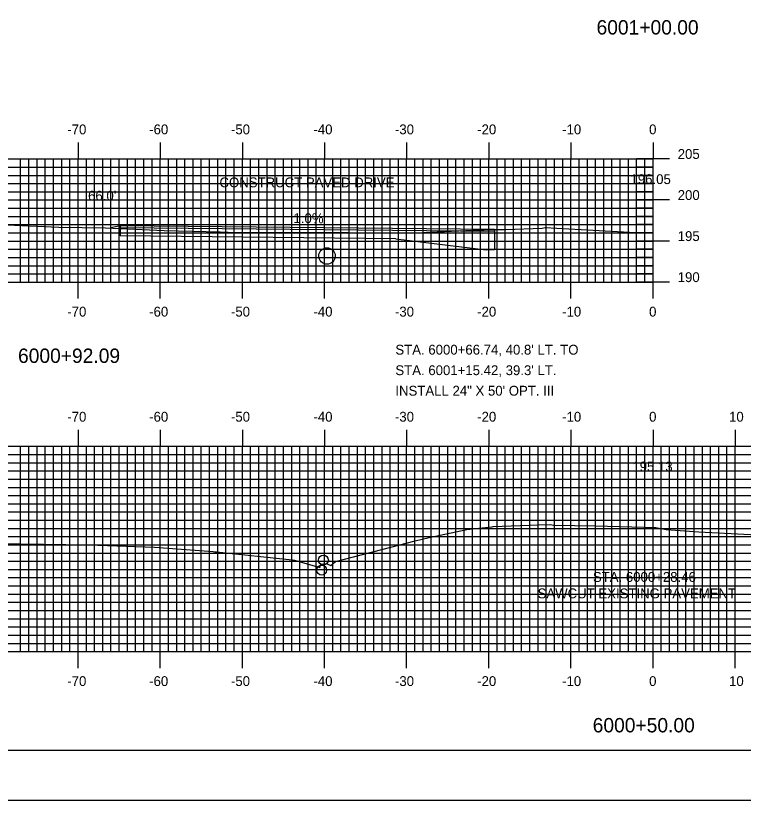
# Model space of a CAD drawing. Extents: x 851300 to 851643, y 366898 to 367118.
# Drawn here: x 851387.9 to 851476.5, y 366898.4 to 366993.9 of the extents above; entities that cross this region are included whole.
import ezdxf

# ---------------------------------------------------------------- set-up
doc = ezdxf.new("R2010")
doc.units = 0
for name, color, linetype in [('ANNOTATION', 7, 'Continuous'), ('BORDER', 7, 'Continuous'), ('D_Drainage_Culvert', 7, 'Continuous'), ('D_Text_Standard', 7, 'Continuous'), ('H_V ANNOTATION', 7, 'Continuous'), ('MAJOR', 7, 'Continuous'), ('MINOR', 7, 'Continuous'), ('PLOT BOUNDARY', 7, 'Continuous'), ('S_Drainage_Invert', 7, 'Continuous'), ('S_Roadway_Centerline', 7, 'Continuous')]:
    doc.layers.add(name, color=color, linetype=linetype)

msp = doc.modelspace()

# ---------------------------------------------------------------- linework, layer by layer
at = {"layer": 'ANNOTATION'}
for p, q in [((851400.605, 366968.345), (851400.605, 366967.095)), ((851434.205, 366966.759), (851445.205, 366965.389))]:
    msp.add_line(p, q, dxfattribs=at)
for points in [[(851446.205, 366967.889), (851400.605, 366968.345), (851399.49, 366968.067)], [(851446.202, 366967.639), (851400.605, 366968.095)], [(851446.205, 366967.889), (851446.205, 366965.389), (851445.205, 366965.389)], [(851434.205, 366966.759), (851400.605, 366967.095)]]:
    msp.add_lwpolyline(points, dxfattribs=at)
at = {"layer": 'BORDER'}
msp.add_lwpolyline([(851315.905, 366904.473), (851635.905, 366904.473), (851635.905, 367114.473), (851315.905, 367114.473)], close=True, dxfattribs=at)
at = {"layer": 'D_Drainage_Culvert'}
msp.add_circle((851425.805, 366964.653), 1, dxfattribs=at)
at = {"layer": 'MAJOR'}
for p, q in [((851395.505, 366978.477), (851395.505, 366976.473)), ((851405.505, 366978.477), (851405.505, 366976.473)), ((851415.505, 366978.477), (851415.505, 366976.473)), ((851425.505, 366978.477), (851425.505, 366976.473)), ((851435.505, 366978.477), (851435.505, 366976.473)), ((851445.505, 366978.477), (851445.505, 366976.473)), ((851455.505, 366978.477), (851455.505, 366976.473)), ((851465.505, 366978.477), (851465.505, 366976.473)), ((851325.505, 366976.473), (851465.505, 366976.473)), ((851325.505, 366976.473), (851465.505, 366976.473)), ((851395.505, 366961.473), (851395.505, 366976.473)), ((851405.505, 366961.473), (851405.505, 366976.473)), ((851415.505, 366961.473), (851415.505, 366976.473)), ((851425.505, 366961.473), (851425.505, 366976.473)), ((851435.505, 366961.473), (851435.505, 366976.473)), ((851445.505, 366961.473), (851445.505, 366976.473)), ((851455.505, 366961.473), (851455.505, 366976.473)), ((851467.509, 366976.473), (851463.501, 366976.473)), ((851465.505, 366961.473), (851465.505, 366976.473)), ((851465.505, 366961.473), (851465.505, 366976.473)), ((851325.505, 366971.473), (851465.505, 366971.473)), ((851467.509, 366971.473), (851463.501, 366971.473)), ((851325.505, 366966.473), (851465.505, 366966.473)), ((851467.509, 366966.473), (851463.501, 366966.473)), ((851325.505, 366961.473), (851465.505, 366961.473)), ((851325.505, 366961.473), (851465.505, 366961.473)), ((851395.505, 366959.469), (851395.505, 366961.473)), ((851405.505, 366959.469), (851405.505, 366961.473)), ((851415.505, 366959.469), (851415.505, 366961.473)), ((851425.505, 366959.469), (851425.505, 366961.473)), ((851435.505, 366959.469), (851435.505, 366961.473)), ((851445.505, 366959.469), (851445.505, 366961.473)), ((851455.505, 366959.469), (851455.505, 366961.473)), ((851467.509, 366961.473), (851463.501, 366961.473)), ((851465.505, 366959.469), (851465.505, 366961.473)), ((851395.505, 366943.477), (851395.505, 366941.473)), ((851405.505, 366943.477), (851405.505, 366941.473)), ((851415.505, 366943.477), (851415.505, 366941.473)), ((851425.505, 366943.477), (851425.505, 366941.473)), ((851435.505, 366943.477), (851435.505, 366941.473)), ((851445.505, 366943.477), (851445.505, 366941.473)), ((851455.505, 366943.477), (851455.505, 366941.473)), ((851465.505, 366943.477), (851465.505, 366941.473)), ((851475.505, 366943.477), (851475.505, 366941.473)), ((851325.505, 366941.473), (851605.505, 366941.473)), ((851325.505, 366941.473), (851605.505, 366941.473)), ((851395.505, 366916.473), (851395.505, 366941.473)), ((851405.505, 366916.473), (851405.505, 366941.473)), ((851415.505, 366916.473), (851415.505, 366941.473)), ((851425.505, 366916.473), (851425.505, 366941.473)), ((851435.505, 366916.473), (851435.505, 366941.473)), ((851445.505, 366916.473), (851445.505, 366941.473)), ((851455.505, 366916.473), (851455.505, 366941.473)), ((851465.505, 366916.473), (851465.505, 366941.473)), ((851475.505, 366916.473), (851475.505, 366941.473)), ((851325.505, 366936.473), (851605.505, 366936.473)), ((851325.505, 366931.473), (851605.505, 366931.473)), ((851325.505, 366926.473), (851605.505, 366926.473)), ((851325.505, 366921.473), (851605.505, 366921.473)), ((851325.505, 366916.473), (851605.505, 366916.473)), ((851325.505, 366916.473), (851605.505, 366916.473)), ((851395.505, 366914.469), (851395.505, 366916.473)), ((851405.505, 366914.469), (851405.505, 366916.473)), ((851415.505, 366914.469), (851415.505, 366916.473)), ((851425.505, 366914.469), (851425.505, 366916.473)), ((851435.505, 366914.469), (851435.505, 366916.473)), ((851445.505, 366914.469), (851445.505, 366916.473)), ((851455.505, 366914.469), (851455.505, 366916.473)), ((851465.505, 366914.469), (851465.505, 366916.473)), ((851475.505, 366914.469), (851475.505, 366916.473))]:
    msp.add_line(p, q, dxfattribs=at)
at = {"layer": 'MINOR'}
for p, q in [((851388.505, 366961.473), (851388.505, 366976.473)), ((851389.505, 366961.473), (851389.505, 366976.473)), ((851390.505, 366961.473), (851390.505, 366976.473)), ((851391.505, 366961.473), (851391.505, 366976.473)), ((851392.505, 366961.473), (851392.505, 366976.473)), ((851393.505, 366961.473), (851393.505, 366976.473)), ((851394.505, 366961.473), (851394.505, 366976.473)), ((851396.505, 366961.473), (851396.505, 366976.473)), ((851397.505, 366961.473), (851397.505, 366976.473)), ((851398.505, 366961.473), (851398.505, 366976.473)), ((851399.505, 366961.473), (851399.505, 366976.473)), ((851400.505, 366961.473), (851400.505, 366976.473)), ((851401.505, 366961.473), (851401.505, 366976.473)), ((851402.505, 366961.473), (851402.505, 366976.473)), ((851403.505, 366961.473), (851403.505, 366976.473)), ((851404.505, 366961.473), (851404.505, 366976.473)), ((851406.505, 366961.473), (851406.505, 366976.473)), ((851407.505, 366961.473), (851407.505, 366976.473)), ((851408.505, 366961.473), (851408.505, 366976.473)), ((851409.505, 366961.473), (851409.505, 366976.473)), ((851410.505, 366961.473), (851410.505, 366976.473)), ((851411.505, 366961.473), (851411.505, 366976.473)), ((851412.505, 366961.473), (851412.505, 366976.473)), ((851413.505, 366961.473), (851413.505, 366976.473)), ((851414.505, 366961.473), (851414.505, 366976.473)), ((851416.505, 366961.473), (851416.505, 366976.473)), ((851417.505, 366961.473), (851417.505, 366976.473)), ((851418.505, 366961.473), (851418.505, 366976.473)), ((851419.505, 366961.473), (851419.505, 366976.473)), ((851420.505, 366961.473), (851420.505, 366976.473)), ((851421.505, 366961.473), (851421.505, 366976.473)), ((851422.505, 366961.473), (851422.505, 366976.473)), ((851423.505, 366961.473), (851423.505, 366976.473)), ((851424.505, 366961.473), (851424.505, 366976.473)), ((851426.505, 366961.473), (851426.505, 366976.473)), ((851427.505, 366961.473), (851427.505, 366976.473)), ((851428.505, 366961.473), (851428.505, 366976.473)), ((851429.505, 366961.473), (851429.505, 366976.473)), ((851430.505, 366961.473), (851430.505, 366976.473)), ((851431.505, 366961.473), (851431.505, 366976.473)), ((851432.505, 366961.473), (851432.505, 366976.473)), ((851433.505, 366961.473), (851433.505, 366976.473)), ((851434.505, 366961.473), (851434.505, 366976.473)), ((851436.505, 366961.473), (851436.505, 366976.473)), ((851437.505, 366961.473), (851437.505, 366976.473)), ((851438.505, 366961.473), (851438.505, 366976.473)), ((851439.505, 366961.473), (851439.505, 366976.473)), ((851440.505, 366961.473), (851440.505, 366976.473)), ((851441.505, 366961.473), (851441.505, 366976.473)), ((851442.505, 366961.473), (851442.505, 366976.473)), ((851443.505, 366961.473), (851443.505, 366976.473)), ((851444.505, 366961.473), (851444.505, 366976.473)), ((851446.505, 366961.473), (851446.505, 366976.473)), ((851447.505, 366961.473), (851447.505, 366976.473)), ((851448.505, 366961.473), (851448.505, 366976.473)), ((851449.505, 366961.473), (851449.505, 366976.473)), ((851450.505, 366961.473), (851450.505, 366976.473)), ((851451.505, 366961.473), (851451.505, 366976.473)), ((851452.505, 366961.473), (851452.505, 366976.473)), ((851453.505, 366961.473), (851453.505, 366976.473)), ((851454.505, 366961.473), (851454.505, 366976.473)), ((851456.505, 366961.473), (851456.505, 366976.473)), ((851457.505, 366961.473), (851457.505, 366976.473)), ((851458.505, 366961.473), (851458.505, 366976.473)), ((851459.505, 366961.473), (851459.505, 366976.473)), ((851460.505, 366961.473), (851460.505, 366976.473)), ((851461.505, 366961.473), (851461.505, 366976.473)), ((851462.505, 366961.473), (851462.505, 366976.473)), ((851463.505, 366961.473), (851463.505, 366976.473)), ((851464.505, 366961.473), (851464.505, 366976.473)), ((851325.505, 366975.473), (851465.505, 366975.473)), ((851465.505, 366975.473), (851463.501, 366975.473)), ((851325.505, 366974.473), (851465.505, 366974.473)), ((851465.505, 366974.473), (851463.501, 366974.473)), ((851325.505, 366973.473), (851465.505, 366973.473)), ((851465.505, 366973.473), (851463.501, 366973.473)), ((851325.505, 366972.473), (851465.505, 366972.473)), ((851465.505, 366972.473), (851463.501, 366972.473)), ((851325.505, 366970.473), (851465.505, 366970.473)), ((851465.505, 366970.473), (851463.501, 366970.473)), ((851325.505, 366969.473), (851465.505, 366969.473)), ((851465.505, 366969.473), (851463.501, 366969.473)), ((851325.505, 366968.473), (851465.505, 366968.473)), ((851465.505, 366968.473), (851463.501, 366968.473)), ((851325.505, 366967.473), (851465.505, 366967.473)), ((851465.505, 366967.473), (851463.501, 366967.473)), ((851325.505, 366965.473), (851465.505, 366965.473)), ((851465.505, 366965.473), (851463.501, 366965.473)), ((851325.505, 366964.473), (851465.505, 366964.473)), ((851465.505, 366964.473), (851463.501, 366964.473)), ((851325.505, 366963.473), (851465.505, 366963.473)), ((851465.505, 366963.473), (851463.501, 366963.473)), ((851325.505, 366962.473), (851465.505, 366962.473)), ((851465.505, 366962.473), (851463.501, 366962.473)), ((851388.505, 366916.473), (851388.505, 366941.473)), ((851389.505, 366916.473), (851389.505, 366941.473)), ((851390.505, 366916.473), (851390.505, 366941.473)), ((851391.505, 366916.473), (851391.505, 366941.473)), ((851392.505, 366916.473), (851392.505, 366941.473)), ((851393.505, 366916.473), (851393.505, 366941.473)), ((851394.505, 366916.473), (851394.505, 366941.473)), ((851396.505, 366916.473), (851396.505, 366941.473)), ((851397.505, 366916.473), (851397.505, 366941.473)), ((851398.505, 366916.473), (851398.505, 366941.473)), ((851399.505, 366916.473), (851399.505, 366941.473)), ((851400.505, 366916.473), (851400.505, 366941.473)), ((851401.505, 366916.473), (851401.505, 366941.473)), ((851402.505, 366916.473), (851402.505, 366941.473)), ((851403.505, 366916.473), (851403.505, 366941.473)), ((851404.505, 366916.473), (851404.505, 366941.473)), ((851406.505, 366916.473), (851406.505, 366941.473)), ((851407.505, 366916.473), (851407.505, 366941.473)), ((851408.505, 366916.473), (851408.505, 366941.473)), ((851409.505, 366916.473), (851409.505, 366941.473)), ((851410.505, 366916.473), (851410.505, 366941.473)), ((851411.505, 366916.473), (851411.505, 366941.473)), ((851412.505, 366916.473), (851412.505, 366941.473)), ((851413.505, 366916.473), (851413.505, 366941.473)), ((851414.505, 366916.473), (851414.505, 366941.473)), ((851416.505, 366916.473), (851416.505, 366941.473)), ((851417.505, 366916.473), (851417.505, 366941.473)), ((851418.505, 366916.473), (851418.505, 366941.473)), ((851419.505, 366916.473), (851419.505, 366941.473)), ((851420.505, 366916.473), (851420.505, 366941.473)), ((851421.505, 366916.473), (851421.505, 366941.473)), ((851422.505, 366916.473), (851422.505, 366941.473)), ((851423.505, 366916.473), (851423.505, 366941.473)), ((851424.505, 366916.473), (851424.505, 366941.473)), ((851426.505, 366916.473), (851426.505, 366941.473)), ((851427.505, 366916.473), (851427.505, 366941.473)), ((851428.505, 366916.473), (851428.505, 366941.473)), ((851429.505, 366916.473), (851429.505, 366941.473)), ((851430.505, 366916.473), (851430.505, 366941.473)), ((851431.505, 366916.473), (851431.505, 366941.473)), ((851432.505, 366916.473), (851432.505, 366941.473)), ((851433.505, 366916.473), (851433.505, 366941.473)), ((851434.505, 366916.473), (851434.505, 366941.473)), ((851436.505, 366916.473), (851436.505, 366941.473)), ((851437.505, 366916.473), (851437.505, 366941.473)), ((851438.505, 366916.473), (851438.505, 366941.473)), ((851439.505, 366916.473), (851439.505, 366941.473)), ((851440.505, 366916.473), (851440.505, 366941.473)), ((851441.505, 366916.473), (851441.505, 366941.473)), ((851442.505, 366916.473), (851442.505, 366941.473)), ((851443.505, 366916.473), (851443.505, 366941.473)), ((851444.505, 366916.473), (851444.505, 366941.473)), ((851446.505, 366916.473), (851446.505, 366941.473)), ((851447.505, 366916.473), (851447.505, 366941.473)), ((851448.505, 366916.473), (851448.505, 366941.473)), ((851449.505, 366916.473), (851449.505, 366941.473)), ((851450.505, 366916.473), (851450.505, 366941.473)), ((851451.505, 366916.473), (851451.505, 366941.473)), ((851452.505, 366916.473), (851452.505, 366941.473)), ((851453.505, 366916.473), (851453.505, 366941.473)), ((851454.505, 366916.473), (851454.505, 366941.473)), ((851456.505, 366916.473), (851456.505, 366941.473)), ((851457.505, 366916.473), (851457.505, 366941.473)), ((851458.505, 366916.473), (851458.505, 366941.473)), ((851459.505, 366916.473), (851459.505, 366941.473)), ((851460.505, 366916.473), (851460.505, 366941.473)), ((851461.505, 366916.473), (851461.505, 366941.473)), ((851462.505, 366916.473), (851462.505, 366941.473)), ((851463.505, 366916.473), (851463.505, 366941.473)), ((851464.505, 366916.473), (851464.505, 366941.473)), ((851466.505, 366916.473), (851466.505, 366941.473)), ((851467.505, 366916.473), (851467.505, 366941.473)), ((851468.505, 366916.473), (851468.505, 366941.473)), ((851469.505, 366916.473), (851469.505, 366941.473)), ((851470.505, 366916.473), (851470.505, 366941.473)), ((851471.505, 366916.473), (851471.505, 366941.473)), ((851472.505, 366916.473), (851472.505, 366941.473)), ((851473.505, 366916.473), (851473.505, 366941.473)), ((851474.505, 366916.473), (851474.505, 366941.473)), ((851325.505, 366940.473), (851605.505, 366940.473)), ((851325.505, 366939.473), (851605.505, 366939.473)), ((851325.505, 366938.473), (851605.505, 366938.473)), ((851325.505, 366937.473), (851605.505, 366937.473)), ((851325.505, 366935.473), (851605.505, 366935.473)), ((851325.505, 366934.473), (851605.505, 366934.473)), ((851325.505, 366933.473), (851605.505, 366933.473)), ((851325.505, 366932.473), (851605.505, 366932.473)), ((851325.505, 366930.473), (851605.505, 366930.473)), ((851325.505, 366929.473), (851605.505, 366929.473)), ((851325.505, 366928.473), (851605.505, 366928.473)), ((851325.505, 366927.473), (851605.505, 366927.473)), ((851325.505, 366925.473), (851605.505, 366925.473)), ((851325.505, 366924.473), (851605.505, 366924.473)), ((851325.505, 366923.473), (851605.505, 366923.473)), ((851325.505, 366922.473), (851605.505, 366922.473)), ((851325.505, 366920.473), (851605.505, 366920.473)), ((851325.505, 366919.473), (851605.505, 366919.473)), ((851325.505, 366918.473), (851605.505, 366918.473)), ((851325.505, 366917.473), (851605.505, 366917.473))]:
    msp.add_line(p, q, dxfattribs=at)
at = {"layer": 'PLOT BOUNDARY'}
msp.add_lwpolyline([(851299.718, 366898.355), (851639.718, 366898.355), (851639.718, 367118.355), (851299.718, 367118.355)], close=True, dxfattribs=at)
at = {"layer": 'S_Drainage_Invert'}
for centre in [(851425.372, 366927.614), (851425.153, 366926.389)]:
    msp.add_circle(centre, 0.6, dxfattribs=at)
at = {"layer": 'S_Roadway_Centerline'}
for points in [[(851381.416, 366968.689), (851393.151, 366968.15), (851398.852, 366968.098), (851405.963, 366967.747), (851412.815, 366967.597), (851414.779, 366967.519), (851418.292, 366967.515), (851422.437, 366967.537), (851424.446, 366967.522), (851428.515, 366967.494), (851433.606, 366967.469), (851437.463, 366967.525), (851443.594, 366967.809), (851444.943, 366967.847), (851445.85, 366967.895), (851447.597, 366967.867), (851451.986, 366968.022), (851452.358, 366968.106), (851453.789, 366968.042), (851463.352, 366967.506), (851465.505, 366967.525)], [(851385.776, 366929.649), (851396.751, 366929.49), (851404.786, 366929.171), (851411.934, 366928.641), (851412.139, 366928.632), (851412.366, 366928.61), (851421.558, 366927.633), (851421.623, 366927.644), (851421.862, 366927.609), (851424.949, 366926.729), (851425.07, 366927.112), (851425.699, 366927.217), (851426.256, 366926.955), (851426.844, 366927.424), (851433.566, 366929.168), (851436.535, 366929.944), (851438.234, 366930.345), (851442.851, 366931.344), (851444.3, 366931.513), (851445.906, 366931.682), (851446.037, 366931.704), (851451.52, 366931.899), (851453.014, 366931.94), (851453.368, 366931.882), (851458.476, 366931.805), (851465.856, 366931.592), (851467.112, 366931.331), (851471.092, 366931.058), (851478.145, 366930.702)]]:
    msp.add_lwpolyline(points, dxfattribs=at)

# ---------------------------------------------------------------- texts
at = {"layer": 'ANNOTATION'}
for s, p in [('CONSTRUCT PAVED DRIVE', (851412.714, 366973.018)), ("66.0'", (851396.72, 366971.389)), ('STA. 6000+28.46', (851458.18, 366924.959)), ('SAWCUT EXISTING PAVEMENT', (851451.449, 366922.955))]:
    msp.add_text(s, height=1.2, dxfattribs=at).set_placement(p)
msp.add_text('1.0%', height=1.2, rotation=359.42706, dxfattribs=at).set_placement((851421.72, 366968.668))
at = {"layer": 'D_Text_Standard'}
for s, p in [("STA. 6000+66.74, 40.8' LT. TO", (851434.131, 366952.64)), ("STA. 6001+15.42, 39.3' LT.", (851434.131, 366950.14)), ('INSTALL 24" X 50\' OPT. III', (851434.131, 366947.64))]:
    msp.add_text(s, height=1.2, dxfattribs=at).set_placement(p)
at = {"layer": 'H_V ANNOTATION'}
for s, height, p in [('6001+00.00', 1.75, (851458.623, 366991.629)), ('-70', 1.2, (851394.188, 366979.473)), ('-60', 1.2, (851404.156, 366979.473)), ('-50', 1.2, (851414.113, 366979.473)), ('-40', 1.2, (851424.156, 366979.473)), ('-30', 1.2, (851434.081, 366979.473)), ('-20', 1.2, (851444.092, 366979.473)), ('-10', 1.2, (851454.435, 366979.473)), ('0', 1.2, (851465.023, 366979.473)), ('205', 1.2, (851468.505, 366976.473)), ('196.05', 1.2, (851462.759, 366973.409)), ('200', 1.2, (851468.505, 366971.473)), ('195', 1.2, (851468.505, 366966.473)), ('190', 1.2, (851468.505, 366961.473)), ('-70', 1.2, (851394.188, 366957.273)), ('-60', 1.2, (851404.156, 366957.273)), ('-50', 1.2, (851414.113, 366957.273)), ('-40', 1.2, (851424.156, 366957.273)), ('-30', 1.2, (851434.081, 366957.273)), ('-20', 1.2, (851444.092, 366957.273)), ('-10', 1.2, (851454.435, 366957.273)), ('0', 1.2, (851465.023, 366957.273)), ('6000+92.09', 1.75, (851388.186, 366951.629)), ('-70', 1.2, (851394.188, 366944.473)), ('-60', 1.2, (851404.156, 366944.473)), ('-50', 1.2, (851414.113, 366944.473)), ('-40', 1.2, (851424.156, 366944.473)), ('-30', 1.2, (851434.081, 366944.473)), ('-20', 1.2, (851444.092, 366944.473)), ('-10', 1.2, (851454.435, 366944.473)), ('0', 1.2, (851465.023, 366944.473)), ('10', 1.2, (851474.756, 366944.473)), ('195.13', 1.2, (851462.984, 366938.409)), ('-70', 1.2, (851394.188, 366912.273)), ('-60', 1.2, (851404.156, 366912.273)), ('-50', 1.2, (851414.113, 366912.273)), ('-40', 1.2, (851424.156, 366912.273)), ('-30', 1.2, (851434.081, 366912.273)), ('-20', 1.2, (851444.092, 366912.273)), ('-10', 1.2, (851454.435, 366912.273)), ('0', 1.2, (851465.023, 366912.273)), ('10', 1.2, (851474.756, 366912.273)), ('6000+50.00', 1.75, (851458.154, 366906.629))]:
    msp.add_text(s, height=height, dxfattribs=at).set_placement(p)
at = {"layer": 'S_Roadway_Centerline'}
for s, p in [('C', (851465.851, 366931.592)), ('C', (851465.851, 366931.592)), ('L', (851465.856, 366931.585)), ('L', (851465.856, 366931.585))]:
    msp.add_text(s, height=0.0146, dxfattribs=at).set_placement(p)

doc.saveas('drawing.dxf')
